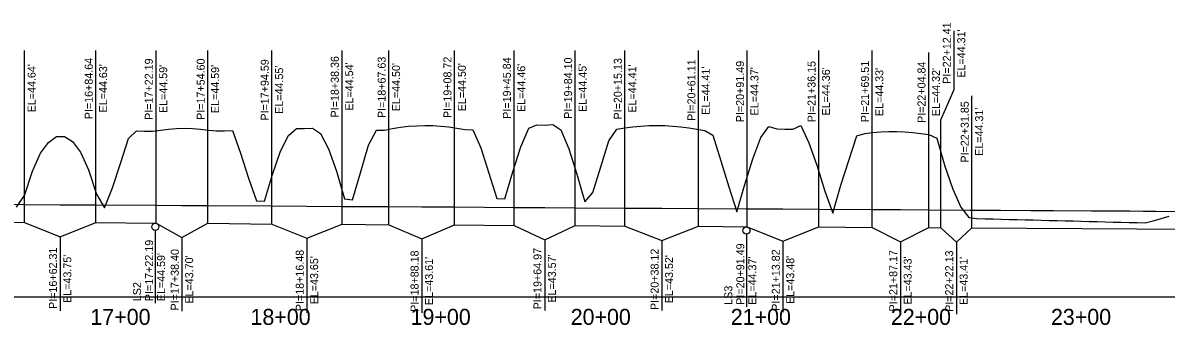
# Model space of a CAD drawing. Extents: x 2394206 to 2397081, y 556531 to 561531.
# Drawn here: x 2394920 to 2395634, y 559014 to 559202 of the extents above; entities that cross this region are included whole.
import ezdxf

# ---------------------------------------------------------------- set-up
doc = ezdxf.new("R2010")
doc.units = 0
for name, color, linetype in [('Default', 7, 'Continuous'), ('Existing ground', 7, 'Continuous'), ('Profile grid', 7, 'Continuous'), ('Proposed bankfull', 7, 'Continuous'), ('Proposed structure lables', 7, 'Continuous'), ('Station lables', 7, 'Continuous')]:
    doc.layers.add(name, color=color, linetype=linetype)

msp = doc.modelspace()

# ---------------------------------------------------------------- linework, layer by layer
at = {"layer": 'Default'}
for p, q in [((2395501.64, 559160.54), (2395501.64, 559197.14)), ((2394920.82, 559077.56), (2394920.82, 559185.03)), ((2394965.48, 559077.51), (2394965.48, 559185.03)), ((2395003.03, 559077.13), (2395003.03, 559185.03)), ((2395035.44, 559077.1), (2395035.44, 559185.03)), ((2395075.43, 559076.64), (2395075.43, 559185.03)), ((2395119.2, 559076.6), (2395119.2, 559185.03)), ((2395148.47, 559076.22), (2395148.47, 559185.03)), ((2395189.56, 559076.18), (2395189.56, 559185.03)), ((2395226.68, 559075.77), (2395226.68, 559185.03)), ((2395264.94, 559075.73), (2395264.94, 559185.03)), ((2395295.97, 559075.32), (2395295.97, 559185.03)), ((2395341.95, 559075.27), (2395341.95, 559185.03)), ((2395372.33, 559074.87), (2395372.33, 559185.03)), ((2395416.99, 559074.83), (2395416.99, 559185.03)), ((2395450.35, 559074.46), (2395450.35, 559185.03)), ((2395485.68, 559074.42), (2395485.68, 559183.69)), ((2395493.25, 559141.75), (2395501.64, 559160.54)), ((2395512.69, 559074.26), (2395512.69, 559156.7)), ((2395493.25, 559074.28), (2395493.25, 559141.75)), ((2394943.15, 559068.65), (2394943.15, 559022.54)), ((2395019.24, 559068.19), (2395019.24, 559022.15)), ((2395097.32, 559067.73), (2395097.32, 559021.18)), ((2395169.02, 559067.3), (2395169.02, 559021.18)), ((2395245.81, 559066.85), (2395245.81, 559022.74)), ((2395318.96, 559066.41), (2395318.96, 559022.74)), ((2395394.66, 559065.96), (2395394.66, 559021.57)), ((2395468.01, 559065.53), (2395468.01, 559021.76)), ((2395502.97, 559065.32), (2395502.97, 559020.4))]:
    msp.add_line(p, q, dxfattribs=at)
at = {"layer": 'Existing ground'}
for points in [[(2394915.84, 559087.24), (2394920.84, 559094.41), (2394925.84, 559109.65), (2394930.84, 559120.76), (2394935.84, 559127.61), (2394940.84, 559131.16), (2394945.84, 559131.32), (2394950.84, 559128.08), (2394955.84, 559121.53), (2394960.84, 559110.4), (2394965.84, 559095.34), (2394970.84, 559086.82), (2394975.84, 559099.12), (2394980.84, 559114.34), (2394985.84, 559130), (2394990.84, 559134.76), (2394995.84, 559134.68), (2395000.84, 559134.6), (2395005.84, 559135.17), (2395010.84, 559135.83), (2395015.84, 559136.24), (2395020.84, 559136.37), (2395025.84, 559136.22), (2395030.84, 559135.8), (2395035.84, 559135.12), (2395040.84, 559134.78), (2395045.84, 559134.88), (2395050.84, 559134.98), (2395055.84, 559120.86), (2395060.84, 559105.32), (2395065.84, 559091.12), (2395070.84, 559090.93), (2395075.84, 559107.47), (2395080.84, 559122.03), (2395085.84, 559131.92), (2395090.84, 559136.34), (2395095.84, 559136.18), (2395100.84, 559136.48), (2395105.84, 559133.09), (2395110.84, 559123.64), (2395115.84, 559109.53), (2395120.84, 559092.25), (2395125.84, 559091.81), (2395130.84, 559108.66), (2395135.84, 559125.79), (2395140.84, 559135.19), (2395145.84, 559135.24), (2395150.84, 559136.19), (2395155.84, 559136.99), (2395160.84, 559137.6), (2395165.84, 559137.99), (2395170.84, 559138.14), (2395175.84, 559138.06), (2395180.84, 559137.75), (2395185.84, 559137.21), (2395190.84, 559136.48), (2395195.84, 559135.69), (2395200.84, 559135.38), (2395205.84, 559124.27), (2395210.84, 559108.43), (2395215.84, 559092.59), (2395220.84, 559092.43), (2395225.84, 559109.29), (2395230.84, 559124.84), (2395235.84, 559136.38), (2395240.84, 559138.47), (2395245.84, 559138.33), (2395250.84, 559138.72), (2395255.84, 559135.5), (2395260.84, 559123.56), (2395265.84, 559107.66), (2395270.84, 559090.53), (2395275.84, 559096.22), (2395280.84, 559112.34)], [(2395280.84, 559112.34), (2395285.84, 559128.46), (2395290.84, 559135.82), (2395295.84, 559136.59), (2395300.84, 559137.28), (2395305.84, 559137.78), (2395310.84, 559138.09), (2395315.84, 559138.2), (2395320.84, 559138.09), (2395325.84, 559137.78), (2395330.84, 559137.27), (2395335.84, 559136.58), (2395340.84, 559135.73), (2395345.84, 559134.91), (2395350.84, 559132.15), (2395355.84, 559116), (2395360.84, 559099.85), (2395365.84, 559084.32), (2395370.84, 559101.24), (2395375.84, 559117.4), (2395380.84, 559130.54), (2395385.84, 559137.44), (2395390.84, 559136.06), (2395395.84, 559135.78), (2395400.84, 559135.84), (2395405.84, 559138.17), (2395410.84, 559127.38), (2395415.84, 559113.3), (2395420.84, 559097.07), (2395425.84, 559083.47), (2395430.84, 559100.89), (2395435.84, 559116.25), (2395440.84, 559131.61), (2395445.84, 559133.1), (2395450.84, 559133.69), (2395455.84, 559134.17), (2395460.84, 559134.43), (2395465.84, 559134.46), (2395470.84, 559134.25), (2395475.84, 559133.82), (2395480.84, 559133.19), (2395485.84, 559132.4), (2395490.84, 559130.21), (2395495.84, 559112.68), (2395500.84, 559098.46), (2395505.84, 559087.07), (2395510.84, 559080.66), (2395515.84, 559080.03), (2395520.84, 559079.91), (2395525.84, 559079.78), (2395530.84, 559079.65), (2395535.84, 559079.53), (2395540.84, 559079.4), (2395545.84, 559079.28), (2395550.84, 559079.15), (2395555.84, 559079.02), (2395560.84, 559078.9), (2395565.84, 559078.77), (2395570.84, 559078.64), (2395575.84, 559078.52), (2395580.84, 559078.39), (2395585.84, 559078.26), (2395590.84, 559078.14), (2395595.84, 559078.01), (2395600.84, 559077.88), (2395605.84, 559077.76), (2395610.84, 559077.63), (2395615.84, 559077.5), (2395620.84, 559077.38), (2395625.84, 559078.72), (2395630.84, 559080.17), (2395635.84, 559081.62)]]:
    msp.add_lwpolyline(points, dxfattribs=at)
at = {"layer": 'Profile grid'}
msp.add_line((2394280.84, 559031.18), (2397080.84, 559031.18), dxfattribs=at)
at = {"layer": 'Proposed bankfull'}
msp.add_lwpolyline([(2394890.44, 559089.01), (2394920.82, 559088.83), (2394943.15, 559088.7), (2394965.48, 559088.57), (2395003.03, 559088.35), (2395019.24, 559088.25), (2395035.44, 559088.16), (2395075.43, 559087.93), (2395097.32, 559087.8), (2395119.2, 559087.67), (2395148.47, 559087.5), (2395169.02, 559087.38), (2395189.56, 559087.26), (2395226.68, 559087.04), (2395245.81, 559086.93), (2395264.94, 559086.81), (2395295.97, 559086.63), (2395318.96, 559086.5), (2395341.95, 559086.36), (2395372.33, 559086.18), (2395394.66, 559086.05), (2395416.99, 559085.92), (2395450.35, 559085.73), (2395468.01, 559085.62), (2395485.68, 559085.52), (2395511.44, 559085.37), (2395530.43, 559085.26), (2395549.42, 559085.15), (2395563.57, 559085.06), (2395587.45, 559084.92), (2395611.34, 559084.78), (2395619.58, 559084.73), (2395627.82, 559084.69), (2395713.53, 559084.18)], dxfattribs=at)
at = {"layer": 'Proposed structure lables'}
for p, q in [((2394890.44, 559077.96), (2394920.82, 559077.56)), ((2394920.82, 559077.56), (2394943.15, 559068.65)), ((2394943.15, 559068.65), (2394965.48, 559077.51)), ((2394965.48, 559077.51), (2395003.03, 559077.13)), ((2395002.55, 559072.57), (2395002.55, 559027.2)), ((2395003.03, 559077.13), (2395019.24, 559068.19)), ((2395019.24, 559068.19), (2395035.44, 559077.1)), ((2395035.44, 559077.1), (2395075.43, 559076.64)), ((2395075.43, 559076.64), (2395097.32, 559067.73)), ((2395097.32, 559067.73), (2395119.2, 559076.6)), ((2395119.2, 559076.6), (2395148.47, 559076.22)), ((2395148.47, 559076.22), (2395169.02, 559067.3)), ((2395169.02, 559067.3), (2395189.56, 559076.18)), ((2395189.56, 559076.18), (2395226.68, 559075.77)), ((2395226.68, 559075.77), (2395245.81, 559066.85)), ((2395245.81, 559066.85), (2395264.94, 559075.73)), ((2395264.94, 559075.73), (2395295.97, 559075.32)), ((2395295.97, 559075.32), (2395318.96, 559066.41)), ((2395318.96, 559066.41), (2395341.95, 559075.27)), ((2395341.95, 559075.27), (2395372.33, 559074.87)), ((2395372.33, 559074.87), (2395394.66, 559065.96)), ((2395394.66, 559065.96), (2395416.99, 559074.83)), ((2395416.99, 559074.83), (2395450.35, 559074.46)), ((2395450.35, 559074.46), (2395468.01, 559065.53)), ((2395468.01, 559065.53), (2395485.68, 559074.42)), ((2395485.68, 559074.42), (2395493.25, 559074.28)), ((2395493.25, 559074.28), (2395502.97, 559065.32)), ((2395502.97, 559065.32), (2395512.69, 559074.26)), ((2395512.69, 559074.26), (2395693.59, 559073.18)), ((2395371.85, 559070.32), (2395371.85, 559024.94))]:
    msp.add_line(p, q, dxfattribs=at)
for centre in [(2395002.55, 559074.86), (2395371.85, 559072.61)]:
    msp.add_ellipse(centre, major_axis=(0, -2.29), ratio=0.950348, dxfattribs=at)

# ---------------------------------------------------------------- texts
for s, p in [('PI=22+12.41', (2395499.49, 559164.19)), ("EL=44.31'", (2395508.49, 559167.97)), ('PI=16+84.64', (2394963.48, 559142.04)), ('PI=17+22.19', (2395001.03, 559141.66)), ('PI=17+54.60', (2395033.44, 559141.62)), ('PI=18+38.36', (2395117.2, 559143.15)), ('PI=18+67.63', (2395146.47, 559142.78)), ('PI=19+08.72', (2395187.56, 559142.78)), ('PI=19+45.84', (2395224.68, 559142.33)), ('PI=19+84.10', (2395262.94, 559142.29)), ('PI=20+15.13', (2395293.97, 559141.88)), ("EL=44.64'", (2394927.82, 559146.33)), ("EL=44.63'", (2394972.48, 559146.29)), ("EL=44.59'", (2395010.03, 559145.9)), ("EL=44.59'", (2395042.44, 559145.87)), ('PI=17+94.59', (2395073.43, 559141.17)), ("EL=44.55'", (2395082.43, 559145.42)), ("EL=44.54'", (2395126.2, 559147.4)), ("EL=44.50'", (2395155.47, 559147.02)), ("EL=44.50'", (2395196.56, 559146.98)), ("EL=44.46'", (2395233.68, 559146.57)), ("EL=44.45'", (2395271.94, 559146.53)), ("EL=44.41'", (2395302.97, 559146.12)), ('PI=20+61.11', (2395339.95, 559141.03)), ("EL=44.41'", (2395348.95, 559144.81)), ('PI=20+91.49', (2395370.33, 559140.16)), ("EL=44.37'", (2395379.33, 559144.41)), ('PI=21+36.15', (2395414.99, 559140.12)), ("EL=44.36'", (2395423.99, 559144.36)), ('PI=21+69.51', (2395448.35, 559140.21)), ("EL=44.33'", (2395457.35, 559143.99)), ('PI=22+04.84', (2395483.68, 559139.71)), ("EL=44.32'", (2395492.68, 559143.95)), ('PI=22+31.85', (2395510.69, 559114.95)), ("EL=44.31'", (2395519.69, 559119.2)), ('PI=17+22.19', (2395001.19, 559028.48)), ('PI=16+62.31', (2394941.15, 559023.63)), ("EL=44.59'", (2395008.69, 559028.48)), ('PI=17+38.40', (2395017.24, 559022.71)), ('PI=18+16.48', (2395095.32, 559022.24)), ('PI=18+88.18', (2395167.02, 559021.82)), ('PI=19+64.97', (2395243.81, 559023.4)), ('PI=20+38.12', (2395316.96, 559022.96)), ('PI=20+91.49', (2395370.49, 559026.23)), ('PI=21+13.82', (2395392.66, 559022.51)), ('PI=21+87.17', (2395466.01, 559022.08)), ('PI=22+22.13', (2395500.97, 559021.82)), ("EL=43.75'", (2394950.15, 559027.41)), ("EL=43.70'", (2395026.24, 559026.96)), ("EL=43.65'", (2395104.32, 559026.49)), ("EL=43.61'", (2395176.02, 559026.06)), ("EL=43.57'", (2395252.81, 559027.6)), ("EL=43.52'", (2395325.96, 559027.16)), ("EL=44.37'", (2395377.99, 559026.23)), ("EL=43.48'", (2395401.66, 559026.71)), ("EL=43.43'", (2395475.01, 559026.28)), ("EL=43.41'", (2395509.97, 559026.07)), ('LS2', (2394993.69, 559028.48)), ('LS3', (2395362.99, 559026.23))]:
    msp.add_text(s, height=5, rotation=90, dxfattribs=at).set_placement(p)
at = {"layer": 'Station lables'}
for s, p in [('17+00', (2394962.05, 559013.68)), ('18+00', (2395062.05, 559013.68)), ('19+00', (2395162.05, 559013.68)), ('20+00', (2395262.05, 559013.68)), ('21+00', (2395362.05, 559013.68)), ('22+00', (2395462.05, 559013.68)), ('23+00', (2395562.05, 559013.68))]:
    msp.add_text(s, height=10, dxfattribs=at).set_placement(p)

doc.saveas('drawing.dxf')
